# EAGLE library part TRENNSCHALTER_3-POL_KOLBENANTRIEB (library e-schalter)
Trennschalter, 3-pol. mit Kolbenantrieb
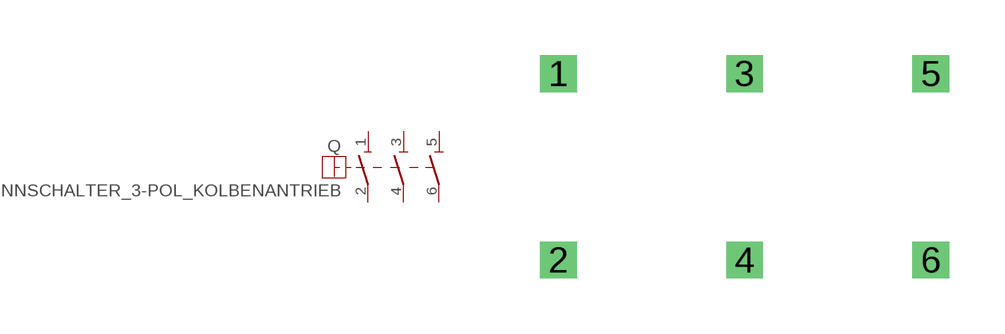
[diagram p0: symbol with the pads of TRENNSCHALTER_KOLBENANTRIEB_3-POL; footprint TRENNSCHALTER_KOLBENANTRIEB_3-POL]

Designator prefix Q

## TRENNSCHALTER_3-POL_KOLBENANTRIEB  [TRENNSCHALTER_KOLBENANTRIEB_3-POL]
1  1  pas
2  2  pas
3  3  pas
4  4  pas
5  5  pas
6  6  pas

## Footprint TRENNSCHALTER_KOLBENANTRIEB_3-POL (pad centres in mm)
Dummy
drill 0.5 pad 1 square: 1 -5.08,2.54; 2 -5.08,-2.54; 3 0,2.54; 4 0,-2.54; 5 5.08,2.54; 6 5.08,-2.54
